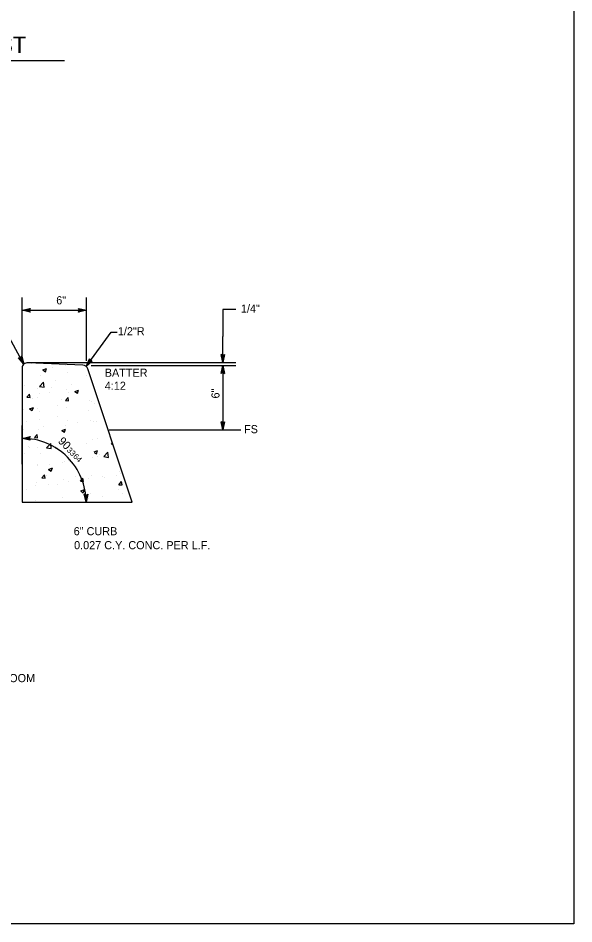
# Model space of a CAD drawing. Extents: x -119017 to -116080, y -104449 to -102845.
# Drawn here: x -117634 to -117223, y -104295 to -103625 of the extents above; entities that cross this region are included whole.
import ezdxf

# ---------------------------------------------------------------- set-up
doc = ezdxf.new("R2010")
doc.units = 0
for name, color, linetype in [('Default', 7, 'Continuous'), ('G-MARK', 7, 'Continuous'), ('G-TEXT', 7, 'Continuous'), ('Misc CnstDet(22)', 7, 'Continuous'), ('Nongeo Data(60)', 7, 'Continuous')]:
    doc.layers.add(name, color=color, linetype=linetype)

msp = doc.modelspace()

# ---------------------------------------------------------------- linework, layer by layer
at = {"layer": 'Default'}
msp.add_lwpolyline([(-119016.83, -102845.16), (-117223.08, -102845.16), (-117223.08, -104295.16), (-119016.83, -104295.16)], close=True, dxfattribs=at)
at = {"layer": 'G-MARK'}
for p, q in [((-117631.19, -103876.47), (-117631.19, -103831.75)), ((-117583.53, -103878.63), (-117583.53, -103831.75)), ((-117631.19, -103841.26), (-117583.53, -103841.26)), ((-117482.77, -103840.54), (-117482.77, -103860.74)), ((-117473.24, -103840.54), (-117482.77, -103840.54)), ((-117482.77, -103879.81), (-117482.77, -103860.74)), ((-117627.84, -103879.81), (-117473.24, -103879.81)), ((-117580.18, -103881.97), (-117473.24, -103881.97)), ((-117482.77, -103881.97), (-117482.77, -103901.05)), ((-117482.77, -103891.51), (-117482.77, -103929.63))]:
    msp.add_line(p, q, dxfattribs=at)
for points in [[(-117629.97, -103881.1), (-117643.6, -103856.11), (-117648.07, -103856.11)], [(-117583.84, -103882.82), (-117565.39, -103857.42), (-117560.92, -103857.42)]]:
    msp.add_lwpolyline(points, dxfattribs=at)
msp.add_arc((-117631.19, -103983.25), 47.27, 359.98578, 90, dxfattribs=at)
at = {"layer": 'G-TEXT'}
for points in [[(-117625.28, -103842.58), (-117631.19, -103841.26), (-117625.28, -103839.95), (-117625.49, -103840.3), (-117629.82, -103841.25), (-117625.49, -103842.23), (-117625.7, -103841.88), (-117628.47, -103841.26), (-117625.7, -103840.65), (-117625.91, -103840.99), (-117627.11, -103841.26), (-117625.91, -103841.53), (-117626.07, -103841.26), (-117625.28, -103839.95), (-117626.07, -103841.26)], [(-117589.44, -103839.94), (-117583.53, -103841.26), (-117589.44, -103842.57), (-117589.23, -103842.22), (-117584.9, -103841.26), (-117589.23, -103840.29), (-117589.02, -103840.64), (-117586.25, -103841.25), (-117589.02, -103841.87), (-117588.81, -103841.52), (-117587.61, -103841.25), (-117588.81, -103840.99), (-117588.65, -103841.26), (-117589.44, -103842.57), (-117588.65, -103841.26)], [(-117631.57, -103875.26), (-117629.97, -103881.1), (-117633.9, -103876.49), (-117633.49, -103876.52), (-117630.61, -103879.89), (-117631.78, -103875.61), (-117631.99, -103875.96), (-117631.24, -103878.69), (-117633.08, -103876.54), (-117632.67, -103876.56), (-117631.88, -103877.49), (-117632.21, -103876.31), (-117632.37, -103876.58), (-117633.9, -103876.49), (-117632.37, -103876.58)], [(-117579.33, -103878.79), (-117583.84, -103882.82), (-117581.46, -103877.25), (-117581.3, -103877.63), (-117583.05, -103881.7), (-117579.73, -103878.75), (-117580.14, -103878.72), (-117582.26, -103880.61), (-117581.14, -103878), (-117580.98, -103878.38), (-117581.46, -103879.5), (-117580.54, -103878.69), (-117580.86, -103878.66), (-117581.46, -103877.25), (-117580.86, -103878.66)], [(-117481.46, -103873.91), (-117482.77, -103879.81), (-117484.08, -103873.91), (-117483.74, -103874.12), (-117482.78, -103878.44), (-117481.81, -103874.12), (-117482.15, -103874.33), (-117482.77, -103877.09), (-117483.39, -103874.33), (-117483.04, -103874.54), (-117482.77, -103875.73), (-117482.5, -103874.53), (-117482.77, -103874.7), (-117484.08, -103873.91), (-117482.77, -103874.7)], [(-117484.09, -103887.88), (-117482.77, -103881.97), (-117481.47, -103887.88), (-117481.81, -103887.67), (-117482.77, -103883.34), (-117483.74, -103887.67), (-117483.4, -103887.46), (-117482.78, -103884.69), (-117482.16, -103887.46), (-117482.51, -103887.25), (-117482.78, -103886.05), (-117483.05, -103887.25), (-117482.77, -103887.09), (-117481.47, -103887.88), (-117482.77, -103887.09)], [(-117481.46, -103923.72), (-117482.77, -103929.63), (-117484.08, -103923.72), (-117483.74, -103923.93), (-117482.78, -103928.26), (-117481.81, -103923.93), (-117482.15, -103924.14), (-117482.77, -103926.91), (-117483.39, -103924.14), (-117483.04, -103924.35), (-117482.77, -103925.55), (-117482.5, -103924.35), (-117482.77, -103924.51), (-117484.08, -103923.72), (-117482.77, -103924.51)], [(-117625.28, -103937.3), (-117631.19, -103935.98), (-117625.28, -103934.67), (-117625.49, -103935.02), (-117629.82, -103935.97), (-117625.49, -103936.95), (-117625.7, -103936.6), (-117628.47, -103935.98), (-117625.7, -103935.37), (-117625.91, -103935.71), (-117627.11, -103935.98), (-117625.91, -103936.25), (-117626.07, -103935.98), (-117625.28, -103934.67), (-117626.07, -103935.98)], [(-117582.62, -103977.35), (-117583.94, -103983.26), (-117585.25, -103977.35), (-117584.9, -103977.56), (-117583.94, -103981.89), (-117582.97, -103977.56), (-117583.32, -103977.77), (-117583.94, -103980.54), (-117584.55, -103977.77), (-117584.2, -103977.98), (-117583.93, -103979.18), (-117583.67, -103977.98), (-117583.94, -103978.14), (-117585.25, -103977.35), (-117583.94, -103978.14)]]:
    msp.add_lwpolyline(points, close=True, dxfattribs=at)
at = {"layer": 'Misc CnstDet(22)'}
for p, q in [((-117583.53, -103841.26), (-117583.53, -103841.26)), ((-117631.19, -103879.81), (-117631.19, -103879.81)), ((-117631.19, -103879.81), (-117631.19, -103879.81)), ((-117631.19, -103879.81), (-117631.19, -103879.81)), ((-117624.18, -103880.53), (-117624.18, -103880.53)), ((-117616.02, -103885.32), (-117613.24, -103884.25)), ((-117616.02, -103885.32), (-117614.05, -103886.66)), ((-117614.05, -103886.66), (-117613.24, -103884.25)), ((-117609.08, -103883.66), (-117609.08, -103883.66)), ((-117602.98, -103881.41), (-117602.98, -103881.41)), ((-117599.14, -103882.35), (-117599.14, -103882.35)), ((-117583.53, -103881.97), (-117583.53, -103881.97)), ((-117583.53, -103881.97), (-117583.53, -103881.97)), ((-117583.53, -103881.97), (-117583.53, -103881.97)), ((-117482.77, -103881.97), (-117482.77, -103881.97)), ((-117617.74, -103889.51), (-117617.74, -103889.51)), ((-117597.7, -103886.98), (-117597.7, -103886.98)), ((-117583.31, -103889.16), (-117583.31, -103889.16)), ((-117629.62, -103897.11), (-117629.62, -103897.11)), ((-117618.46, -103897.67), (-117615.4, -103894.45)), ((-117618.46, -103897.67), (-117614.96, -103898.23)), ((-117614.93, -103898.23), (-117615.4, -103894.45)), ((-117609.58, -103898.01), (-117609.58, -103898.01)), ((-117606.45, -103893.14), (-117606.45, -103893.14)), ((-117594.54, -103896.04), (-117594.54, -103896.04)), ((-117627.69, -103905.52), (-117625.75, -103903.24)), ((-117627.69, -103905.52), (-117625.31, -103905.71)), ((-117625.31, -103905.71), (-117625.75, -103903.24)), ((-117619.52, -103899.33), (-117619.52, -103899.33)), ((-117618.24, -103902.74), (-117618.24, -103902.74)), ((-117610.71, -103901.7), (-117610.71, -103901.7)), ((-117599.2, -103907.99), (-117597.29, -103905.71)), ((-117598.17, -103900.2), (-117598.17, -103900.2)), ((-117596.95, -103901.86), (-117596.95, -103901.86)), ((-117592.32, -103901.33), (-117589.53, -103900.27)), ((-117592.32, -103901.33), (-117590.35, -103902.64)), ((-117590.35, -103902.64), (-117589.53, -103900.27)), ((-117589.5, -103902.61), (-117589.5, -103902.61)), ((-117576.09, -103904.27), (-117576.06, -103904.24)), ((-117576.09, -103904.27), (-117576.06, -103904.27)), ((-117623.53, -103906.14), (-117623.53, -103906.14)), ((-117620.09, -103905.83), (-117620.09, -103905.83)), ((-117604.98, -103911.71), (-117604.98, -103911.71)), ((-117602.32, -103907.05), (-117602.32, -103907.05)), ((-117599.2, -103907.99), (-117596.82, -103908.21)), ((-117596.82, -103908.21), (-117597.29, -103905.74)), ((-117581.12, -103907.93), (-117581.12, -103907.93)), ((-117579.9, -103908.4), (-117579.9, -103908.4)), ((-117578.03, -103910.43), (-117578.03, -103910.43)), ((-117629.97, -103914.99), (-117629.97, -103914.99)), ((-117625.68, -103914.12), (-117622.9, -103913.06)), ((-117625.68, -103914.12), (-117623.71, -103915.46)), ((-117623.71, -103915.46), (-117622.9, -103913.06)), ((-117620.02, -103913.68), (-117620.02, -103913.68)), ((-117618.71, -103915.96), (-117618.71, -103915.96)), ((-117598.67, -103913.43), (-117598.67, -103913.43)), ((-117581.78, -103915.74), (-117581.78, -103915.74)), ((-117628.09, -103923.69), (-117628.09, -103923.69)), ((-117618.62, -103921.91), (-117618.62, -103921.91)), ((-117604.92, -103919.72), (-117604.92, -103919.72)), ((-117597.42, -103922.78), (-117597.42, -103922.78)), ((-117590.35, -103924.06), (-117590.35, -103924.06)), ((-117580.4, -103922.75), (-117580.4, -103922.75)), ((-117578.5, -103923.66), (-117578.5, -103923.66)), ((-117576.21, -103923.69), (-117576.21, -103923.69)), ((-117631.19, -103955.08), (-117631.19, -103926.44)), ((-117630.47, -103929.35), (-117630.47, -103929.35)), ((-117619.18, -103929.19), (-117619.18, -103929.19)), ((-117615.43, -103927.38), (-117615.43, -103927.38)), ((-117601.98, -103930.13), (-117599.2, -103929.07)), ((-117601.98, -103930.13), (-117600.01, -103931.44)), ((-117600.01, -103931.44), (-117599.2, -103929.07)), ((-117599.14, -103926.63), (-117599.14, -103926.63)), ((-117566.96, -103929.63), (-117469.36, -103929.63)), ((-117484.24, -103929.63), (-117484.24, -103929.63)), ((-117482.77, -103929.63), (-117482.77, -103929.63)), ((-117622.15, -103935.38), (-117620.24, -103933.1)), ((-117622.15, -103935.38), (-117619.81, -103935.6)), ((-117619.81, -103935.6), (-117620.24, -103933.1)), ((-117579, -103936.88), (-117579, -103936.88)), ((-117575.81, -103936.45), (-117575.81, -103936.45)), ((-117626.34, -103942.2), (-117626.34, -103942.2)), ((-117625.87, -103943.04), (-117625.87, -103943.04)), ((-117619.68, -103942.39), (-117619.68, -103942.39)), ((-117613.21, -103942.95), (-117610.11, -103939.73)), ((-117613.21, -103942.95), (-117609.67, -103943.48)), ((-117609.67, -103943.48), (-117610.11, -103939.73)), ((-117606.58, -103943.42), (-117606.58, -103943.42)), ((-117605.14, -103943.08), (-117605.14, -103943.08)), ((-117583.41, -103939.45), (-117583.41, -103939.45)), ((-117578, -103946.02), (-117575.49, -103945.05)), ((-117576.31, -103947.45), (-117575.49, -103945.05)), ((-117565.21, -103940.36), (-117564.36, -103939.39)), ((-117565.21, -103940.36), (-117563.99, -103940.48)), ((-117562.74, -103944.89), (-117562.74, -103944.89)), ((-117629.75, -103947.39), (-117629.75, -103947.39)), ((-117617.96, -103947.52), (-117617.96, -103947.52)), ((-117597.07, -103952.14), (-117597.07, -103952.14)), ((-117596.76, -103948.42), (-117596.76, -103948.42)), ((-117579.47, -103950.11), (-117579.47, -103950.11)), ((-117577.62, -103946.55), (-117576.31, -103947.45)), ((-117575.56, -103949.33), (-117575.56, -103949.33)), ((-117573.9, -103948.17), (-117573.9, -103948.17)), ((-117570.83, -103949.52), (-117567.74, -103946.3)), ((-117570.83, -103949.52), (-117567.3, -103950.08)), ((-117567.3, -103950.08), (-117567.74, -103946.3)), ((-117631.19, -103958.43), (-117631.19, -103958.43)), ((-117620.21, -103956.12), (-117620.21, -103956.12)), ((-117620.15, -103955.62), (-117620.15, -103955.62)), ((-117611.64, -103958.93), (-117608.86, -103957.84)), ((-117611.64, -103958.93), (-117609.67, -103960.24)), ((-117611.24, -103955.4), (-117611.24, -103955.4)), ((-117609.67, -103960.24), (-117608.86, -103957.87)), ((-117601.29, -103954.08), (-117601.29, -103954.08)), ((-117600.1, -103953.08), (-117600.1, -103953.08)), ((-117616.65, -103965.25), (-117614.74, -103962.96)), ((-117616.65, -103965.25), (-117614.27, -103965.47)), ((-117614.27, -103965.47), (-117614.74, -103962.96)), ((-117613.05, -103963.28), (-117613.05, -103963.28)), ((-117591.85, -103964.15), (-117591.85, -103964.15)), ((-117590.25, -103959.62), (-117590.25, -103959.62)), ((-117588.16, -103967.75), (-117586.25, -103965.47)), ((-117585.78, -103967.97), (-117586.25, -103965.47)), ((-117581.9, -103966.03), (-117581.9, -103966.03)), ((-117579.97, -103963.31), (-117579.97, -103963.31)), ((-117571.65, -103964.47), (-117571.65, -103964.47)), ((-117570.65, -103965.06), (-117570.65, -103965.06)), ((-117561.7, -103963.15), (-117561.7, -103963.15)), ((-117559.58, -103960.53), (-117559.58, -103960.53)), ((-117558.73, -103962.06), (-117558.73, -103962.06)), ((-117621.71, -103971.06), (-117621.71, -103971.06)), ((-117620.65, -103968.84), (-117620.65, -103968.84)), ((-117611.77, -103969.75), (-117611.77, -103969.75)), ((-117605.05, -103970), (-117605.05, -103970)), ((-117600.57, -103966.31), (-117600.57, -103966.31)), ((-117596.73, -103967.78), (-117596.73, -103967.78)), ((-117588.16, -103967.75), (-117585.78, -103967.97)), ((-117559.67, -103970.25), (-117557.76, -103967.97)), ((-117559.67, -103970.25), (-117557.29, -103970.44)), ((-117557.29, -103970.44), (-117557.76, -103967.97)), ((-117628.22, -103974), (-117628.22, -103974)), ((-117587.94, -103974.91), (-117585.16, -103973.85)), ((-117587.94, -103974.91), (-117585.97, -103976.25)), ((-117585.97, -103976.25), (-117585.16, -103973.85)), ((-117580.43, -103976.54), (-117580.43, -103976.54)), ((-117572.15, -103978.82), (-117572.15, -103978.82)), ((-117560.05, -103973.75), (-117560.05, -103973.75)), ((-117557.11, -103976.85), (-117557.11, -103976.85)), ((-117631.19, -103983.26), (-117631.19, -103983.26)), ((-117631.19, -103983.26), (-117631.19, -103983.26)), ((-117631.19, -103983.26), (-117631.19, -103983.26)), ((-117621.12, -103982.07), (-117621.12, -103982.07)), ((-117618.77, -103983.26), (-117618.77, -103983.26)), ((-117615.43, -103983.26), (-117574.4, -103983.26)), ((-117601.07, -103979.51), (-117601.07, -103979.51)), ((-117582.09, -103980.13), (-117582.09, -103980.13))]:
    msp.add_line(p, q, dxfattribs=at)
for points in [[(-117631.19, -103883.97), (-117631.19, -103983.26)], [(-117631.19, -103983.26), (-117549.73, -103983.26), (-117582.66, -103884.5)], [(-117586.22, -103881.85), (-117627.03, -103880)]]:
    msp.add_lwpolyline(points, dxfattribs=at)
for centre, start, end in [((-117627.22, -103883.97), 87.39744, 180), ((-117586.4, -103885.82), 19.1899, 87.39744)]:
    msp.add_arc(centre, 3.97, start, end, dxfattribs=at)
at = {"layer": 'Nongeo Data(60)'}
msp.add_line((-117844.15, -103656.47), (-117599.79, -103656.47), dxfattribs=at)

# ---------------------------------------------------------------- texts
at = {"layer": 'Misc CnstDet(22)'}
for s, height, p in [('REMOVABLE GUARD POST', 12, (-117838.72, -103650.85)), ('6"', 6, (-117606, -103836.83)), ('1/2"R', 6, (-117560.42, -103859.73)), ('BATTER', 6, (-117570.12, -103890.41)), ('4:12', 6, (-117570.12, -103900.08)), ('FS', 6, (-117467.06, -103932.16)), ('6" CURB', 6, (-117593.11, -104007.67)), ('0.027 C.Y. CONC. PER L.F.', 6, (-117592.81, -104017.99)), ('IMMEDIATELY AFTER FINISHING OPERATIONS ARE COMPLETE, THE CONTRACTOR SHALL PROVIDE BROOM', 6, (-118045.16, -104116.33))]:
    msp.add_text(s, height=height, dxfattribs=at).set_placement(p)
for s, height, rotation, p in [('1/4"', 6, 0.001, (-117469.4, -103842.99)), ('6"', 6, 90, (-117485.23, -103906.49)), ('90', 6, 315, (-117605.09, -103938.55)), ('33', 4.2, 315, (-117598.5, -103945.14)), ('64', 4.2, 315, (-117593.88, -103949.75))]:
    msp.add_text(s, height=height, rotation=rotation, dxfattribs=at).set_placement(p)

doc.saveas('drawing.dxf')
